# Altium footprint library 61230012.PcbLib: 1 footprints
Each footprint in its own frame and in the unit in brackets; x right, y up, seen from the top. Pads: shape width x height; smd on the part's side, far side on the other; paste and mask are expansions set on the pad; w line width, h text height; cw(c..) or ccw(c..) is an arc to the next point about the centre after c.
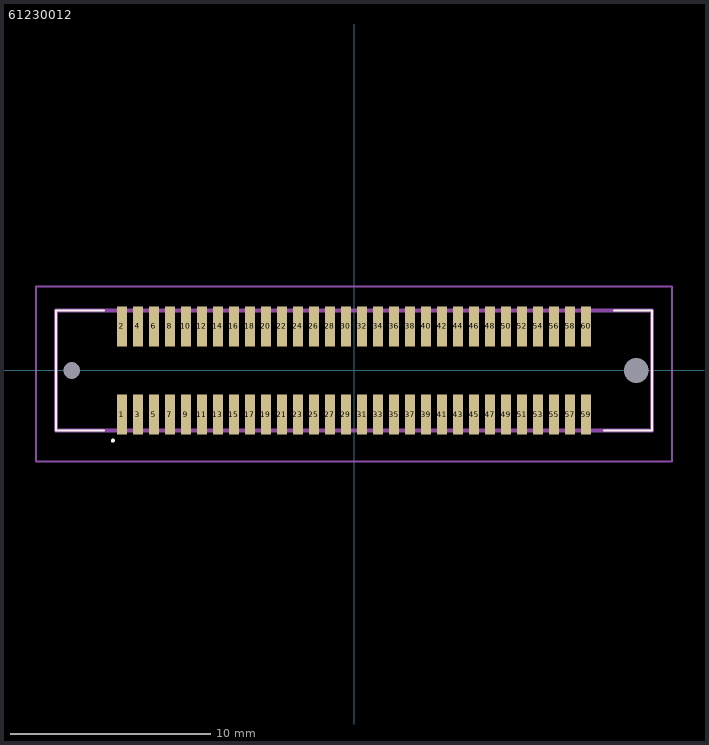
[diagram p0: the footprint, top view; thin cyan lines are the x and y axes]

## 61230012 [mm]
pads (62):
  rect 0.5x2 smd: 1(-11.6,-2.2) 2(-11.6,2.2) 3(-10.8,-2.2) 4(-10.8,2.2) 5(-10,-2.2) 6(-10,2.2) 7(-9.2,-2.2) 8(-9.2,2.2) 9(-8.4,-2.2) 10(-8.4,2.2) 11(-7.6,-2.2) 12(-7.6,2.2) 13(-6.8,-2.2) 14(-6.8,2.2) 15(-6,-2.2) 16(-6,2.2) 17(-5.2,-2.2) 18(-5.2,2.2) 19(-4.4,-2.2) 20(-4.4,2.2) 21(-3.6,-2.2) 22(-3.6,2.2) 23(-2.8,-2.2) 24(-2.8,2.2) 25(-2,-2.2) 26(-2,2.2) 27(-1.2,-2.2) 28(-1.2,2.2) 29(-0.4,-2.2) 30(-0.4,2.2) 31(0.4,-2.2) 32(0.4,2.2) 33(1.2,-2.2) 34(1.2,2.2) 35(2,-2.2) 36(2,2.2) 37(2.8,-2.2) 38(2.8,2.2) 39(3.6,-2.2) 40(3.6,2.2) 41(4.4,-2.2) 42(4.4,2.2) 43(5.2,-2.2) 44(5.2,2.2) 45(6,-2.2) 46(6,2.2) 47(6.8,-2.2) 48(6.8,2.2) 49(7.6,-2.2) 50(7.6,2.2) 51(8.4,-2.2) 52(8.4,2.2) 53(9.2,-2.2) 54(9.2,2.2) 55(10,-2.2) 56(10,2.2) 57(10.8,-2.2) 58(10.8,2.2) 59(11.6,-2.2) 60(11.6,2.2)
  round 0.415 hole 0.83 unplated: MH1(-14.1,0)
  round 0.615 hole 1.23 unplated: MH2(14.1,0)
Top Overlay:
  lines w0.1: -12.5,-3 -14.9,-3 -14.9,3 -12.5,3 ; 12.5,-3 14.9,-3 14.9,3 13,3 ; -12.1,-3.5 cw(c-12.05,-3.5) -12,-3.5 ; -12.1,-3.5 -12.1,-3.5 ; -12.1,-3.5 ccw(c-12.05,-3.5) -12,-3.5 ; -12,-3.5 -12,-3.5
Mechanical 15:
  lines w0.2: -14.9,-3 14.9,-3 14.9,3 -14.9,3 -14.9,-3
Mechanical 20:
  lines w0.1: -15.9,-4.55 15.9,-4.55 15.9,4.2 -15.9,4.2 -15.9,-4.55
